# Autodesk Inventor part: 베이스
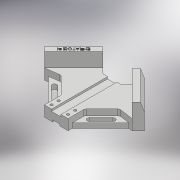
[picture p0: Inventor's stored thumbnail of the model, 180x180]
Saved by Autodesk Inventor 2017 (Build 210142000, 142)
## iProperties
Part Number: 베이스
Material: 일반
Document SubType Name: Modeling
Designer: 222
Density: 1 g/cm^3
Appearance: 기본값
Mass: 211.712 g
Surface Area: 407.173 cm^2
Volume: 211.712 cm^3
Author: 222
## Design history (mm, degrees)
sketch "스케치2"
  geometry: L1 (-84.853, 0)-(0, 84.853); L2 (0, 84.853)-(84.853, 0); L3 (84.853, 0)-(0, -84.853); L4 (0, -84.853)-(-84.853, 0); 1 further point
  constraints: 8 end point, 3 equal length, 2 horizontal alignment, 2 vertical alignment, 1 perpendicular, 1 point on line
  dimensions: "d2" = 120 distance of L1.end L2.end
extrude "돌출1" new body sketch "스케치2" distance "d4" = 18; taper "d5" = 0 deg
sketch "스케치3"
  geometry: L1 (-84.853, -64.853)-(84.853, -64.853); L2 (84.853, -64.853)-(84.853, -84.853); L3 (84.853, -84.853)-(-84.853, -84.853); L4 (-84.853, -84.853)-(-84.853, -64.853); 4 further points
  constraints: 8 end point, 2 parallel, 2 vertical alignment, 1 horizontal, 1 midpoint, 1 perpendicular
  dimensions: "d6" = 20 distance between parallel lines of L3 L1
extrude "돌출2" cut sketch "스케치3" stored distance "d7" = 18; taper "d8" = 0 deg
sketch "스케치4"
  geometry: L1 (-20, -64.853)-(20, -64.853) reference; L2 (35.355, 49.497)-(16.005, 30.147); L3 (-35.355, 49.497)-(-16.005, 30.147); L4 (0, 84.853)-(-84.853, 0) reference; L5 (84.853, 0)-(0, 84.853) reference; L6 (-16.005, 30.147)-(16.005, 30.147); 1 further point
  constraints: 6 end point, 2 point on line, 1 horizontal
  dimensions: "d13" = 50 distance from line of L3 L4.start; "d14" = 50 distance from line of L4.start L2; "d15" = 95 distance between parallel lines of L1 L6
extrude "돌출3" cut sketch "스케치4" stored distance "d16" = 18; taper "d17" = 0 deg
sketch "스케치5"
  geometry: L1 (20, -64.853)-(-20, -64.853) reference; L2 (-20, -64.853)-(-84.853, 0) reference; L3 (-84.853, 0)-(-35.355, 49.497) reference; L4 (-35.355, 49.497)-(-16.005, 30.147) reference; L5 (-16.005, 30.147)-(16.005, 30.147) reference; L6 (16.005, 30.147)-(35.355, 49.497) reference; L7 (35.355, 49.497)-(84.853, 0) reference; L8 (84.853, 0)-(20, -64.853) reference; L9 (-74.246, -10.607)-(-24.749, 38.891); L10 (24.749, 38.891)-(74.246, -10.607); 1 further point
  constraints: 4 end point, 4 point on line, 2 parallel
  dimensions: "d18" = 15 distance between parallel lines of L3 L9; "d19" = 15 distance between parallel lines of L7 L10
extrude "돌출4" join sketch "스케치5" distance "d20" = 24; taper "d21" = 0 deg
chamfer "모따기1" distance "d22" = 5; stored, may be unused: second distance "d23" = 15, angle "d24" = 45 deg
chamfer "모따기2" distance "d25" = 5; stored, may be unused: second distance "d26" = 15, angle "d27" = 45 deg
sketch "스케치8"
  geometry: L1 (-8, 30.147)-(8, 30.147); L2 (8, 30.147)-(8, -64.853); L3 (8, -64.853)-(-8, -64.853); L4 (-8, -64.853)-(-8, 30.147); L5 (16.005, 30.147)-(-16.005, 30.147) reference; L6 (-20, -64.853)-(20, -64.853) reference; 2 further points
  constraints: 8 end point, 2 parallel, 2 point on line, 1 horizontal, 1 midpoint, 1 perpendicular, 1 vertical alignment
  dimensions: "d31" = 16 distance between parallel lines of L2 L4
extrude "돌출5" cut sketch "스케치8" distance "d32" = 3.5; taper "d33" = 0 deg
sketch "스케치9"
  geometry: L1 (6, -64.853)-(-6, -64.853); L2 (-6, -64.853)-(-6, 30.147); L3 (-6, 30.147)-(6, 30.147); L4 (6, 30.147)-(6, -64.853); L5 (16.005, 30.147)-(-16.005, 30.147) reference; L6 (-20, -64.853)-(20, -64.853) reference; 2 further points
  constraints: 8 end point, 2 parallel, 2 point on line, 1 horizontal, 1 midpoint, 1 perpendicular, 1 vertical alignment
  dimensions: "d34" = 12 distance between parallel lines of L2 L4
extrude "돌출6" cut sketch "스케치9" distance "d35" = 3; taper "d36" = 0 deg
sketch "스케치10"
  geometry: L1 (-84.853, 0)-(-20, -64.853) reference; L2 (-20, -36.569)-(-20, -64.853); L3 (-63.64, -21.213)-(-49.497, -7.071); L4 (-35.355, 49.497)-(-84.853, 0) reference; L5 (-100.63, 44.061)-(-70.711, 14.142); L6 (-49.497, -7.071)-(-20, -36.569); L7 (-74.246, -10.607)-(-24.749, 38.891) reference; L8 (-49.497, -7.071)-(-74.246, -10.607); 1 further point
  constraints: 10 end point, 3 point on line, 2 parallel, 2 perpendicular, 1 vertical
  dimensions: "d39" = 20 distance from line of point (0, 0) L2; "d40" = 30 distance between parallel lines of L4 L3
extrude "돌출7" cut sketch "스케치10" distance "d41" = 10; taper "d42" = 0 deg
sketch "스케치11"
  geometry: L1 (-49.497, -7.071)-(-20, -36.569) reference; L2 (-74.246, -10.607)-(-49.497, -7.071) reference; L3 (-20, -64.853)-(-74.246, -10.607) reference; L4 (-20, -36.569)-(-20, -64.853) reference; L5 (-20, -57.782)-(-68.059, -9.723); 1 further point
  constraints: 2 end point, 2 point on line
  dimensions: "d43" = 5 distance between parallel lines of L3 L5
extrude "돌출8" cut sketch "스케치11" stored distance "d44" = 10; taper "d45" = 0 deg
sketch "스케치12"
  geometry: L1 (-35.355, 49.497)-(-84.853, 0) reference; L2 (-81.317, -3.536)-(-74.246, -10.607) reference; L3 (-52.326, -21.213)-(-32.527, -41.012); L4 (-26.87, -35.355)-(-46.669, -15.556); A1 r 4 centre (-49.497, -18.385) between (-46.669, -15.556) and (-52.326, -21.213); A2 r 4 centre (-29.698, -38.184) between (-32.527, -41.012) and (-26.87, -35.355); 1 further point
  constraints: 4 end point, 4 point on circle, 4 tangent, 2 centre point
  dimensions: "d48" = 8 diameter of A1; "d49" = 38 distance from line of L1 A1.centre; "d50" = 12 distance from line of L2 A1.centre; "d51" = 8 diameter of A2; "d52" = 66 distance from line of L1 A2.centre; "d53" = 12 distance from line of L2 A2.centre
extrude "돌출9" cut sketch "스케치12" stored distance "d54" = 10; taper "d55" = 0 deg
sketch "스케치13"
  geometry: L1 (-20, -64.853)-(-8, -64.853) reference; C1 r 2.25 at (-14, -58.853); C2 r 2.25 at (-14, -46.853); 1 further point
  constraints: 2 centre point, 1 vertical alignment
  dimensions: "d56" = 4.5 diameter of C1; "d57" = 14 horizontal distance of point (0, 0) C1.centre; "d58" = 6 distance from line of L1 C1.centre; "d59" = 4.5 diameter of C2; "d60" = 12 distance of C1.centre C2.centre
extrude "돌출10" cut sketch "스케치13" distance "d61" = 8; taper "d62" = 0 deg
sketch "스케치14"
  geometry: C1 r 4 at (0, 0); C2 r 2.25 at (0, 0) reference; C3 r 4 at (0, -12); C4 r 2.25 at (0, -12) reference; 1 further point
  constraints: 2 centre point, 2 concentric
  dimensions: "d63" = 8 diameter of C1; "d64" = 8 diameter of C3
extrude "돌출11" cut sketch "스케치14" stored distance "d65" = 8; taper "d66" = 0 deg
fillet "모깎기1" dims "d67" = 5
fillet "모깎기2" dims "d68" = 5
sketch "스케치15"
  geometry: L1 (-74.246, -10.607)-(-24.749, 38.891) reference; L2 (-31.82, 45.962)-(-35.355, 49.497) reference; 2 further points
  constraints: 1 other
  dimensions: "d69" = 5 distance from line of L1 point (-53.033, 17.678); "d70" = 35 distance from line of L2 point (-53.033, 17.678)
feature "엠보싱1" sketch "스케치15" dims "d2" = 120, "d71" = 0.5, "d72" = 0
node "솔리드1"
mirror "미러1"
mirror "미러2"
mirror "미러3"
node "투영된 루프1"
node "절단 모서리 투영1"
other parameters: "d9" = 95, "d11" = 45 deg, "d12" = 45 deg
